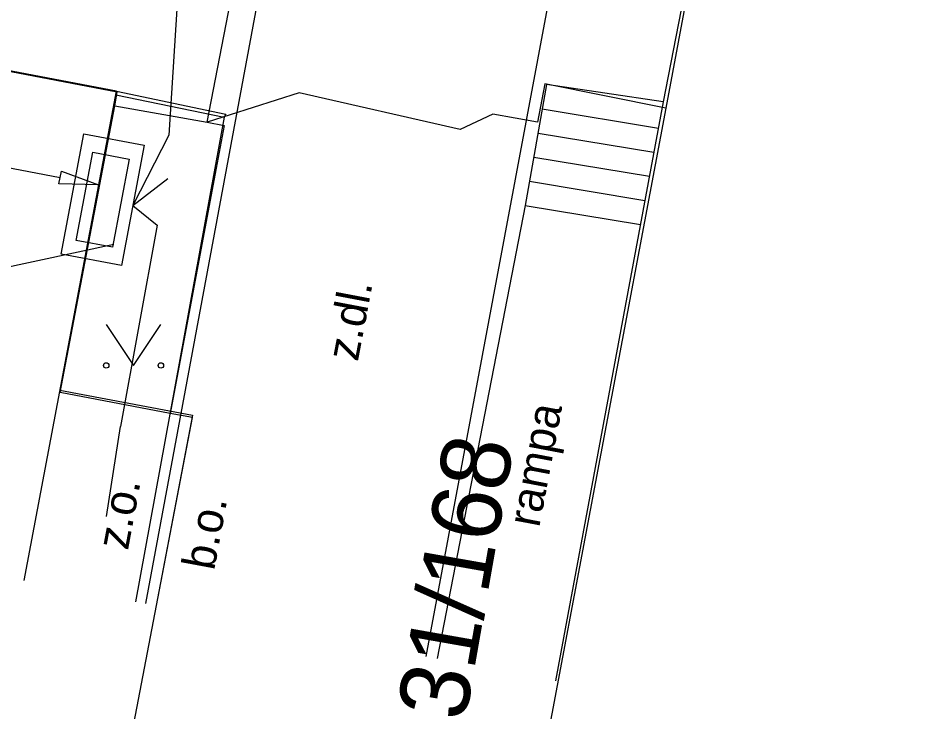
# Model space of a CAD drawing. Extents: x -601602 to -600882, y -1162594 to -1161950.
# Drawn here: x -601201.23 to -601190.09, y -1162109.04 to -1162100.55 of the extents above; entities that cross this region are included whole.
import ezdxf

# ---------------------------------------------------------------- set-up
doc = ezdxf.new("R2010")
doc.units = 0
for name, color, linetype in [('IS_EON_NN', 7, 'Continuous'), ('KN_Hranice parcel', 7, 'Continuous'), ('KN_Parcelní čísla', 7, 'Continuous'), ('KN_Pop  PČ popisy', 7, 'Continuous'), ('KN_Značky kultur', 7, 'Continuous'), ('VRSTVA 40', 7, 'Continuous'), ('Vrstva 7', 7, 'Continuous')]:
    doc.layers.add(name, color=color, linetype=linetype)

# ---------------------------------------------------------------- blocks, each defined once
blk = doc.blocks.new('132_9')
at = {"layer": 'IS_EON_NN'}
for points in [[(-1.5, 1.5), (1.5, 1.5), (1.5, 0), (-1.5, 0)], [(-1.1, 1.2), (1.1, 1.2), (1.1, 0.3), (-1.1, 0.3)]]:
    blk.add_lwpolyline(points, close=True, dxfattribs=at)
blk = doc.blocks.new('1029_72')
at = {"layer": 'KN_Pop  PČ popisy'}
for p, q in [((-2.935, -0.624), (-2.06, 0.074)), ((0, 0), (-2.935, -0.624)), ((-2.935, -0.624), (-1.852, -0.906))]:
    blk.add_line(p, q, dxfattribs=at)

msp = doc.modelspace()

# ---------------------------------------------------------------- linework, layer by layer
at = {"layer": 'IS_EON_NN'}
msp.add_line((-601200.15, -1162106.65), (-601199.98, -1162105.55), dxfattribs=at)
for points in [[(-601195.29, -1162079.33), (-601196.24, -1162082.25), (-601196.78, -1162083.59), (-601199.26, -1162094.69), (-601199.63, -1162096.11), (-601199.77, -1162097.15), (-601199.68, -1162098.25), (-601199.5, -1162099.07), (-601199.27, -1162100.11), (-601199.39, -1162101.98), (-601199.83, -1162102.84)], [(-601199.83, -1162102.84), (-601199.4, -1162102.51)], [(-601199.83, -1162102.84), (-601199.53, -1162103.08), (-601199.98, -1162105.55)]]:
    msp.add_lwpolyline(points, dxfattribs=at)
at = {"layer": 'KN_Hranice parcel'}
msp.add_line((-601200.05, -1162101.62), (-601198.92, -1162101.82), dxfattribs=at)
for points in [[(-601200.05, -1162101.62), (-601200.02, -1162101.45), (-601257.65, -1162090.43), (-601258.35, -1162094.11), (-601259.98, -1162093.8), (-601271.27, -1162152.93), (-601269.66, -1162153.24), (-601270.36, -1162156.92), (-601270.25, -1162156.94)], [(-601198.92, -1162101.82), (-601197.94, -1162096.76), (-601202.1, -1162095.83)], [(-601180.66, -1162099.38), (-601192.45, -1162097.1), (-601193.3, -1162101.65)], [(-601193.3, -1162101.65), (-601194.78, -1162101.35), (-601194.87, -1162101.82), (-601195.42, -1162101.72), (-601195.82, -1162101.91), (-601197.79, -1162101.46), (-601198.92, -1162101.82)], [(-601199.37, -1162105.39), (-601200.72, -1162105.13), (-601200.05, -1162101.62)], [(-601193.3, -1162101.65), (-601194.89, -1162110.11), (-601194.38, -1162110.21)], [(-601198.92, -1162101.82), (-601198.71, -1162101.86), (-601199.37, -1162105.39)], [(-601200.42, -1162112.35), (-601199.1, -1162105.44), (-601199.37, -1162105.39)]]:
    msp.add_lwpolyline(points, dxfattribs=at)
at = {"layer": 'KN_Značky kultur'}
for p, q in [((-601200.155, -1162104.297), (-601199.82, -1162104.8)), ((-601199.82, -1162104.8), (-601199.485, -1162104.297))]:
    msp.add_line(p, q, dxfattribs=at)
for centre in [(-601200.155, -1162104.8), (-601199.485, -1162104.8)]:
    msp.add_circle(centre, 0.0335, dxfattribs=at)
at = {"layer": 'VRSTVA 40'}
for p, q in [((-601208.708, -1162100.972), (-601200.72, -1162102.497)), ((-601200.086, -1162101.735), (-601200.249, -1162102.587))]:
    msp.add_line(p, q, dxfattribs=at)
msp.add_lwpolyline([(-601200.735, -1162102.575), (-601200.705, -1162102.418), (-601200.249, -1162102.587)], close=True, dxfattribs=at)
at = {"layer": 'Vrstva 7'}
for p, q in [((-601192.47, -1162097.1), (-601193.33, -1162101.57)), ((-601199.67, -1162107.719), (-601198.1, -1162099.28)), ((-601196.233, -1162108.368), (-601194.67, -1162100.01)), ((-601200.03, -1162101.44), (-601204.532, -1162100.581)), ((-601194.76, -1162101.36), (-601195.02, -1162102.84)), ((-601193.33, -1162101.57), (-601194.76, -1162101.36)), ((-601201.162, -1162107.437), (-601200.03, -1162101.44)), ((-601200.038, -1162101.483), (-601198.71, -1162101.76)), ((-601200.03, -1162101.44), (-601198.69, -1162101.72)), ((-601193.33, -1162101.57), (-601194.651, -1162108.666)), ((-601198.69, -1162101.72), (-601198.71, -1162101.76)), ((-601194.812, -1162101.658), (-601193.39, -1162101.893)), ((-601198.71, -1162101.76), (-601199.798, -1162107.695)), ((-601194.864, -1162101.953), (-601193.445, -1162102.188)), ((-601194.916, -1162102.249), (-601193.5, -1162102.483)), ((-601194.968, -1162102.544), (-601193.555, -1162102.778)), ((-601195.02, -1162102.84), (-601196.1, -1162108.393)), ((-601195.02, -1162102.84), (-601193.61, -1162103.073)), ((-601200.722, -1162105.104), (-601199.1, -1162105.41)), ((-601199.1, -1162105.41), (-601199.545, -1162107.743))]:
    msp.add_line(p, q, dxfattribs=at)

# ---------------------------------------------------------------- block references
at = {"layer": 'IS_EON_NN', "xscale": 0.5, "yscale": 0.5, "rotation": 79.3236443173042}
msp.add_blockref('132_9', (-601199.83, -1162102.84), dxfattribs=at)
at = {"layer": 'KN_Pop  PČ popisy'}
msp.add_blockref('1029_72', (-601200.06, -1162103.32), dxfattribs=at)

# ---------------------------------------------------------------- texts
at = {"layer": 'KN_Parcelní čísla'}
msp.add_text('1331/168', height=0.85, rotation=80, dxfattribs=at).set_placement((-601195.979, -1162110.421))
at = {"layer": 'Vrstva 7'}
for s, rotation, p in [('z.dl.', 79.2301, (-601197.073, -1162104.761)), ('rampa', 79.2301, (-601194.851, -1162106.796)), ('z.o.', 79.4716, (-601199.89, -1162107.074)), ('b.o.', 79.4716, (-601198.834, -1162107.323))]:
    msp.add_text(s, height=0.4, rotation=rotation, dxfattribs=at).set_placement(p)

doc.saveas('drawing.dxf')
